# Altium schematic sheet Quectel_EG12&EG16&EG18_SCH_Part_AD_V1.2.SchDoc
size A1
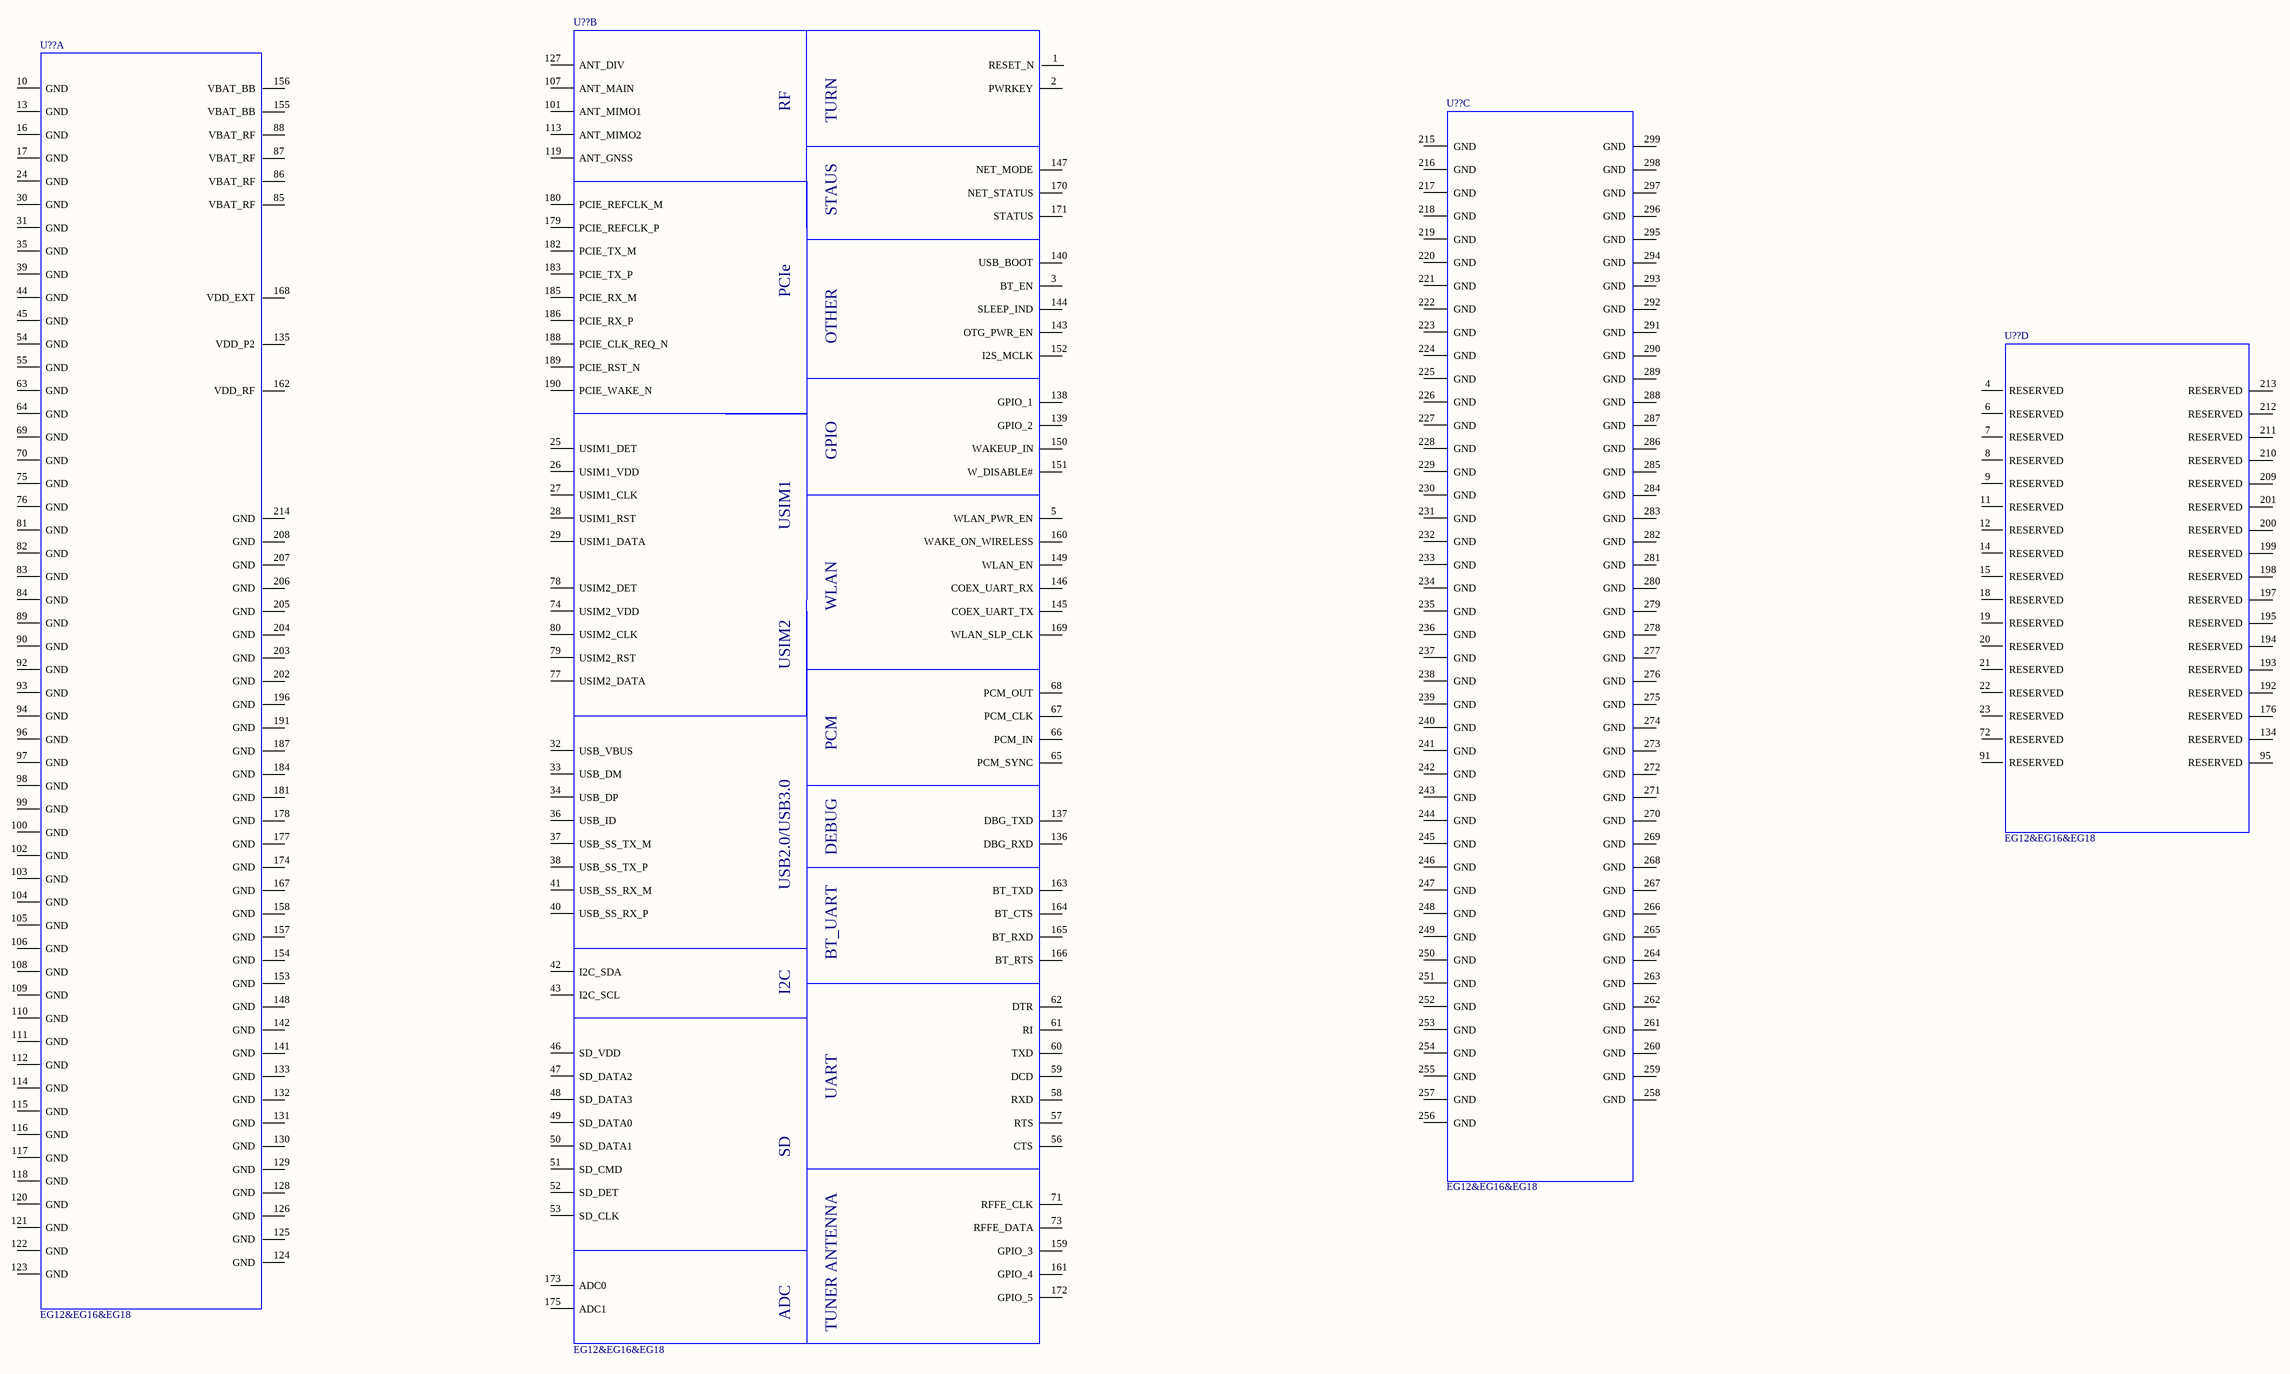
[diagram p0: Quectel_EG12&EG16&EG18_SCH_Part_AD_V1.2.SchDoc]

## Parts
(Parts that share a designator on the sheet are numbered #1, #2 ... from top to bottom, then left to right.)
U??#1  EG12&EG16&EG18  (part D of 4)
U??#2  EG12&EG16&EG18  (part B of 4)
U??#3  EG12&EG16&EG18  (part C of 4)
U??#4  EG12&EG16&EG18  (part A of 4)

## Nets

Not connected (* = marked no-connect by the designer): U??#1 4(RESERVED) 6(RESERVED) 7(RESERVED) 8(RESERVED) 9(RESERVED) 11(RESERVED) 12(RESERVED) 14(RESERVED) 15(RESERVED) 18(RESERVED) 19(RESERVED) 20(RESERVED) 21(RESERVED) 22(RESERVED) 23(RESERVED) 72(RESERVED) 91(RESERVED) 95(RESERVED) 134(RESERVED) 176(RESERVED) 192(RESERVED) 193(RESERVED) 194(RESERVED) 195(RESERVED) 197(RESERVED) 198(RESERVED) 199(RESERVED) 200(RESERVED) 201(RESERVED) 209(RESERVED) 210(RESERVED) 211(RESERVED) 212(RESERVED) 213(RESERVED); U??#2 1(RESET_N) 2(PWRKEY) 3(BT_EN) 5(WLAN_PWR_EN) 25(USIM1_DET) 26(USIM1_VDD) 27(USIM1_CLK) 28(USIM1_RST) 29(USIM1_DATA) 32(USB_VBUS) 33(USB_DM) 34(USB_DP) 36(USB_ID) 37(USB_SS_TX_M) 38(USB_SS_TX_P) 40(USB_SS_RX_P) 41(USB_SS_RX_M) 42(I2C_SDA) 43(I2C_SCL) 46(SD_VDD) 47(SD_DATA2) 48(SD_DATA3) 49(SD_DATA0) 50(SD_DATA1) 51(SD_CMD) 52(SD_DET) 53(SD_CLK) 56(CTS) 57(RTS) 58(RXD) 59(DCD) 60(TXD) 61(RI) 62(DTR) 65(PCM_SYNC) 66(PCM_IN) 67(PCM_CLK) 68(PCM_OUT) 71(RFFE_CLK) 73(RFFE_DATA) 74(USIM2_VDD) 77(USIM2_DATA) 78(USIM2_DET) 79(USIM2_RST) 80(USIM2_CLK) 101(ANT_MIMO1) 107(ANT_MAIN) 113(ANT_MIMO2) 119(ANT_GNSS) 127(ANT_DIV) 136(DBG_RXD) 137(DBG_TXD) 138(GPIO_1) 139(GPIO_2) 140(USB_BOOT) 143(OTG_PWR_EN) 144(SLEEP_IND) 145(COEX_UART_TX) 146(COEX_UART_RX) 147(NET_MODE) 149(WLAN_EN) 150(WAKEUP_IN) 151(W_DISABLE#) 152(I2S_MCLK) 159(GPIO_3) 160(WAKE_ON_WIRELESS) 161(GPIO_4) 163(BT_TXD) 164(BT_CTS) 165(BT_RXD) 166(BT_RTS) 169(WLAN_SLP_CLK) 170(NET_STATUS) 171(STATUS) 172(GPIO_5) 173(ADC0) 175(ADC1) 179(PCIE_REFCLK_P) 180(PCIE_REFCLK_M) 182(PCIE_TX_M) 183(PCIE_TX_P) 185(PCIE_RX_M) 186(PCIE_RX_P) 188(PCIE_CLK_REQ_N) 189(PCIE_RST_N) 190(PCIE_WAKE_N); U??#3 215(GND) 216(GND) 217(GND) 218(GND) 219(GND) 220(GND) 221(GND) 222(GND) 223(GND) 224(GND) 225(GND) 226(GND) 227(GND) 228(GND) 229(GND) 230(GND) 231(GND) 232(GND) 233(GND) 234(GND) 235(GND) 236(GND) 237(GND) 238(GND) 239(GND) 240(GND) 241(GND) 242(GND) 243(GND) 244(GND) 245(GND) 246(GND) 247(GND) 248(GND) 249(GND) 250(GND) 251(GND) 252(GND) 253(GND) 254(GND) 255(GND) 256(GND) 257(GND) 258(GND) 259(GND) 260(GND) 261(GND) 262(GND) 263(GND) 264(GND) 265(GND) 266(GND) 267(GND) 268(GND) 269(GND) 270(GND) 271(GND) 272(GND) 273(GND) 274(GND) 275(GND) 276(GND) 277(GND) 278(GND) 279(GND) 280(GND) 281(GND) 282(GND) 283(GND) 284(GND) 285(GND) 286(GND) 287(GND) 288(GND) 289(GND) 290(GND) 291(GND) 292(GND) 293(GND) 294(GND) 295(GND) 296(GND) 297(GND) 298(GND) 299(GND); U??#4 10(GND) 13(GND) 16(GND) 17(GND) 24(GND) 30(GND) 31(GND) 35(GND) 39(GND) 44(GND) 45(GND) 54(GND) 55(GND) 63(GND) 64(GND) 69(GND) 70(GND) 75(GND) 76(GND) 81(GND) 82(GND) 83(GND) 84(GND) 85(VBAT_RF) 86(VBAT_RF) 87(VBAT_RF) 88(VBAT_RF) 89(GND) 90(GND) 92(GND) 93(GND) 94(GND) 96(GND) 97(GND) 98(GND) 99(GND) 100(GND) 102(GND) 103(GND) 104(GND) 105(GND) 106(GND) 108(GND) 109(GND) 110(GND) 111(GND) 112(GND) 114(GND) 115(GND) 116(GND) 117(GND) 118(GND) 120(GND) 121(GND) 122(GND) 123(GND) 124(GND) 125(GND) 126(GND) 128(GND) 129(GND) 130(GND) 131(GND) 132(GND) 133(GND) 135(VDD_P2) 141(GND) 142(GND) 148(GND) 153(GND) 154(GND) 155(VBAT_BB) 156(VBAT_BB) 157(GND) 158(GND) 162(VDD_RF) 167(GND) 168(VDD_EXT) 174(GND) 177(GND) 178(GND) 181(GND) 184(GND) 187(GND) 191(GND) 196(GND) 202(GND) 203(GND) 204(GND) 205(GND) 206(GND) 207(GND) 208(GND) 214(GND)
